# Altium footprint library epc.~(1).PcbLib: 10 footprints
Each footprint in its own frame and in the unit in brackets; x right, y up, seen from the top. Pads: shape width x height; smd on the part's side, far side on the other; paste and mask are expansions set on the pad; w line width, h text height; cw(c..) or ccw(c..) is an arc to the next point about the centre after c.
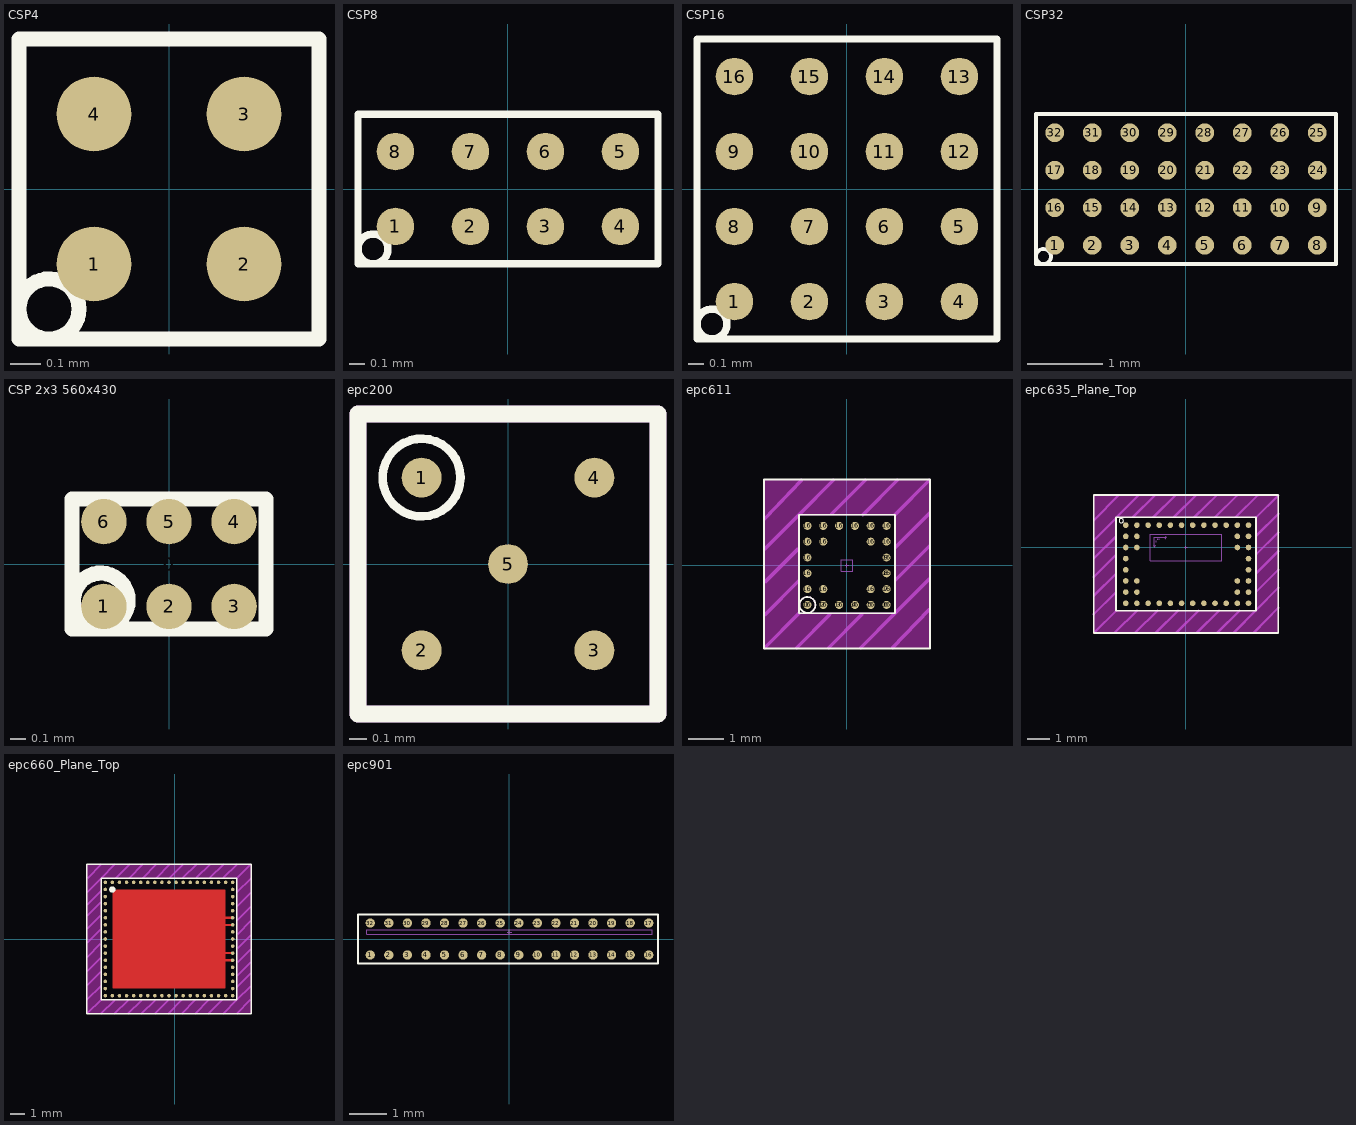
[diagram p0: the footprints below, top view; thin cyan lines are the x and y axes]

## CSP4 [mm] "CSP4 Dual Photodiode"
height 0.3
pads (4):
  round 0.25 smd mask+0.05: 1(-0.25,-0.25) 2(0.25,-0.25) 3(0.25,0.25) 4(-0.25,0.25)
Top Overlay:
  circle w0.05: c-0.4,-0.4 r0.1
  lines w0.05: -0.5,-0.5 -0.5,0.5 0.5,0.5 0.5,-0.5 -0.5,-0.5
3D body "epc300-CSP4_001.STEP": height 0.23, standoff -0.01, extent -0.5,-0.5 0.5,0.5

## CSP8 [mm] "CSP8 Quad Photodiode-Array"
height 0.3
pads (8):
  round 0.25 smd mask+0.05: 1(-0.75,-0.25) 2(-0.25,-0.25) 3(0.25,-0.25) 4(0.75,-0.25) 5(0.75,0.25) 6(0.25,0.25) 7(-0.25,0.25) 8(-0.75,0.25)
Top Overlay:
  circle w0.05: c-0.9,-0.4 r0.1
  lines w0.05: -1,-0.5 1,-0.5 1,0.5 -1,0.5 -1,-0.5
3D body "epc310-CSP8-001.STEP": height 0.24, standoff 0, extent -1,-0.5 1,0.5

## CSP16 [mm] "CSP16 Octa Photodiode-Array"
height 0.3
pads (16):
  round 0.25 smd mask+0.05: 1(-0.75,-0.75) 2(-0.25,-0.75) 3(0.25,-0.75) 4(0.75,-0.75) 5(0.75,-0.25) 6(0.25,-0.25) 7(-0.25,-0.25) 8(-0.75,-0.25) 9(-0.75,0.25) 10(-0.25,0.25) 11(0.25,0.25) 12(0.75,0.25) 13(0.75,0.75) 14(0.25,0.75) 15(-0.25,0.75) 16(-0.75,0.75)
Top Overlay:
  circle w0.05: c-0.9,-0.9 r0.1
  lines w0.05: -1,-1 -1,1 1,1 1,-1 -1,-1
3D body "epc320-CSP16-001.STEP": height 0.24, standoff 0, extent -1,-1 1,1

## CSP32 [mm] "CSP16 hexa Photodiode-Array"
height 0.3
pads (32):
  round 0.25 smd mask+0.05: 1(-1.75,-0.75) 2(-1.25,-0.75) 3(-0.75,-0.75) 4(-0.25,-0.75) 5(0.25,-0.75) 6(0.75,-0.75) 7(1.25,-0.75) 8(1.75,-0.75) 9(1.75,-0.25) 10(1.25,-0.25) 11(0.75,-0.25) 12(0.25,-0.25) 13(-0.25,-0.25) 14(-0.75,-0.25) 15(-1.25,-0.25) 16(-1.75,-0.25) 17(-1.75,0.25) 18(-1.25,0.25) 19(-0.75,0.25) 20(-0.25,0.25) 21(0.25,0.25) 22(0.75,0.25) 23(1.25,0.25) 24(1.75,0.25) 25(1.75,0.75) 26(1.25,0.75) 27(0.75,0.75) 28(0.25,0.75) 29(-0.25,0.75) 30(-0.75,0.75) 31(-1.25,0.75) 32(-1.75,0.75)
Top Overlay:
  circle w0.05: c-1.9,-0.9 r0.1
  lines w0.05: -2,-1 -2,1 2,1 2,-1 -2,-1
3D body "epc330-CSP32-001.STEP": height 0.24, standoff 0, extent -2,-1 2,1

## CSP 2x3 560x430 [mm] "CSP 2x3"
height 0.3
pads (7):
  rect 1.98x1.56 on Top Solder: 0(0,0)
  round 0.3 smd paste+0 mask-0.16: 1(-0.43,-0.28)
  round 0.3 smd paste+0 mask-1.6: 2(0,-0.28) 3(0.43,-0.28) 4(0.43,0.28) 5(0,0.28)
  round 0.3 smd paste+0 mask-0.3: 6(-0.43,0.28)
Top Overlay:
  circle w0.1: c-0.45,-0.24 r0.18
  lines w0.1: -0.64,-0.43 0.64,-0.43 0.64,0.43 -0.64,0.43 -0.64,-0.43
3D body: height 0.3, standoff 0.2, extent -0.6,-0.45 0.575,0.425
3D body: height 0.2, standoff 0, extent -0.526,-0.374 -0.327,-0.175
3D body: height 0.2, standoff 0, extent -0.101,-0.375 0.098,-0.175
3D body: height 0.2, standoff 0, extent 0.325,-0.375 0.524,-0.175
3D body: height 0.2, standoff 0, extent 0.326,0.175 0.525,0.375
3D body: height 0.2, standoff 0, extent -0.1,0.175 0.099,0.375
3D body: height 0.2, standoff 0, extent -0.525,0.175 -0.326,0.374

## epc200 [mm]
pads (5):
  round 0.23 smd paste+0.035 mask+0.05: 1(-0.5,0.5) 2(-0.5,-0.5) 3(0.5,-0.5) 4(0.5,0.5) 5(0,0)
Top Overlay:
  circle w0.05: c-0.5,0.5 r0.225
  lines w0.1: -0.867,-0.867 -0.867,0.867 0.867,0.867 0.867,-0.867 -0.867,-0.867
Mechanical 4:
  lines w0.1: -0.867,-0.867 -0.867,0.867 0.867,0.867 0.867,-0.867 -0.867,-0.867
3D body "epc200-CSP5.STEP": height 0.24, standoff -0.01, extent -0.875,-0.875 0.875,0.875

## epc611 [mm]
height 0.25
pads (49):
  round 0.229 smd paste-0.254 mask+0.111: 1(-1.125,-1.125) 2(-0.675,-1.125) 3(-0.225,-1.125) 4(0.225,-1.125) 5(0.675,-1.125) 6(1.125,-1.125) 7(1.125,-0.675) 8(1.125,-0.225) 9(1.125,0.225) 10(1.125,0.675) 11(1.125,1.125) 12(0.675,1.125) 13(0.225,1.125) 14(-0.225,1.125) 15(-0.675,1.125) 16(-1.125,1.125) 17(-1.125,0.675) 18(-1.125,0.225) 19(-1.125,-0.225) 20(-1.125,-0.675) 21(-0.675,-0.675) 22(0.675,-0.675) 23(0.675,0.675) 24(-0.675,0.675)
  round 0.3 on Top Paste paste+0.057 mask-0.508: 16(-1.125,-1.125) 16(-1.125,-0.675) 16(-1.125,-0.225) 16(-1.125,0.225) 16(-1.125,1.125) 16(-0.675,-1.125) 16(-0.675,-0.675) 16(-0.675,0.675) 16(-0.675,1.125) 16(-0.225,-1.125) 16(-0.225,1.125) 16(0.225,1.125) 16(0.675,-1.125) 16(0.675,-0.675) 16(0.675,0.675) 16(0.675,1.125) 16(1.125,-1.125) 16(1.125,-0.675) 16(1.125,-0.225) 16(1.125,0.225) 16(1.125,0.675) 16(1.125,1.125)
  round 0.3 on Top Paste paste+0.057 mask-0.108: 16(-1.125,0.675)
  round 0.3 on Top Paste paste+0.057 mask+0.051: 16(0.225,-1.125)
  round 0.229 smd paste-0.254 mask+0.051: 21(-0.675,-0.675)
Top Layer keep-out:
  region: -2.365,2.445 -2.365,-2.365 -1.365,-2.365 -1.365,2.445
  region: 2.365,2.445 -2.365,2.445 -2.365,1.445 2.365,1.445
  region: 2.365,-2.365 2.365,2.445 1.365,2.445 1.365,-2.365
  rectangle: -2.365,-2.365 2.365,-1.365
Top Overlay:
  circle w0.05: c-1.125,-1.125 r0.225
  lines w0.05: -2.365,-2.365 -2.365,2.445 2.365,2.445 2.365,-2.365 -2.365,-2.365 ; -1.365,-1.365 1.365,-1.365 1.365,1.445 -1.365,1.445 -1.365,-1.365
Mechanical 2:
  lines w0.1: -2.343,-2.343 -1.365,-1.365 ; -2.343,0.467 -1.365,1.445 -0.387,2.423 ; -2.338,1.333 -1.297,2.423 ; -2.336,-1.404 -1.388,-0.456 ; -2.335,-0.471 -1.41,0.454 ; -1.433,-2.343 -0.487,-1.397 ; -0.523,-2.343 0.426,-1.393 ; -0.429,1.471 0.522,2.423 ; 0.387,-2.343 1.365,-1.365 2.343,-0.387 ; 0.454,1.445 1.432,2.423 ; 1.297,-2.343 2.333,-1.258 ; 1.365,1.445 2.343,2.423 ; 1.385,-0.413 2.343,0.545 ; 1.389,0.523 2.347,1.481
  text "ATTENTION:  / 1mm clearance arount the epc611.  / Don't place components within this frame." at -2.45,-3.97 h0.25
Mechanical 4:
  circle w0.05: c-1.125,-1.125 r0.225
  lines w0.01: -0.05,0 0.05,0 ; 0,-0.05 0,0.05 ; -0.16,-0.16 0.16,-0.16 0.16,0.16 -0.16,0.16 -0.16,-0.16
  lines w0.05: -1.365,-1.365 -1.365,1.445 1.365,1.445 1.365,-1.365 -1.365,-1.365
  text "col7" at 0.2,-0.505 h0.2
  text "row7" at 0.21,-0.2 h0.2
  text "row0" at 0.21,0.12 h0.2
  text "col0" at -0.115,-0.505 h0.2
3D body: height 0.2, standoff 0, extent 1.026,0.125 1.224,0.325
3D body: height 0.2, standoff 0, extent 1.026,-0.325 1.224,-0.125
3D body: height 0.2, standoff 0, extent 1.026,-0.775 1.224,-0.575
3D body: height 0.2, standoff 0, extent 0.576,-0.775 0.774,-0.575
3D body: height 0.2, standoff 0, extent -0.774,-0.775 -0.576,-0.575
3D body: height 0.2, standoff 0, extent -1.224,-0.775 -1.026,-0.575
3D body: height 0.2, standoff 0, extent -1.224,-0.325 -1.026,-0.125
3D body: height 0.2, standoff 0, extent -1.224,0.125 -1.026,0.325
3D body: height 0.2, standoff 0, extent -1.224,0.575 -1.026,0.775
3D body: height 0.2, standoff 0, extent -0.774,0.575 -0.576,0.775
3D body: height 0.2, standoff 0, extent 0.576,0.575 0.774,0.775
3D body: height 0.2, standoff 0, extent 1.026,0.575 1.224,0.775
3D body: height 0.2, standoff 0, extent 0.126,1.025 0.324,1.225
3D body: height 0.2, standoff 0, extent -0.324,1.025 -0.126,1.225
3D body: height 0.2, standoff 0, extent -0.774,1.025 -0.576,1.225
3D body: height 0.2, standoff 0, extent -1.224,1.025 -1.026,1.225
3D body: height 0.2, standoff 0, extent -1.224,-1.225 -1.026,-1.025
3D body: height 0.2, standoff 0, extent 0.576,-1.225 0.774,-1.025
3D body: height 0.2, standoff 0, extent 1.026,-1.225 1.224,-1.025
3D body: height 0.2, standoff 0, extent 1.026,1.025 1.224,1.225
3D body: height 0.2, standoff 0, extent 0.576,1.025 0.774,1.225
3D body: height 0.2, standoff 0, extent -0.324,-1.225 -0.126,-1.025
3D body: height 0.2, standoff 0, extent 0.126,-1.225 0.324,-1.025
3D body: height 0.2, standoff 0, extent -0.774,-1.225 -0.576,-1.025
3D body: height 0.25, standoff 0.19, extent -1.365,-1.365 1.365,1.445

## epc635_Plane_Top [mm] "CSP44 epc635_PL_Top"
height 0.26
pads (44):
  round 0.25 smd paste+0.025 mask+0.05: 1(-2.7,1) 2(-2.7,0.5) 3(-2.7,0) 4(-2.7,-0.5) 5(-2.7,-1) 6(-2.7,-1.5) 7(-2.7,-2) 8(-2.7,-2.5) 9(-2.2,-2.5) 10(-1.7,-2.5) 11(-1.2,-2.5) 12(-0.7,-2.5) 13(-0.2,-2.5) 14(0.3,-2.5) 15(0.8,-2.5) 16(1.3,-2.5) 17(1.8,-2.5) 18(2.3,-2.5) 19(2.8,-2.5) 20(2.8,-2) 21(2.8,-1.5) 22(2.8,-1) 23(2.8,-0.5) 24(2.8,0) 25(2.8,0.5) 26(2.8,1) 27(2.3,1) 28(1.8,1) 29(1.3,1) 30(0.8,1) 31(0.3,1) 32(-0.2,1) 33(-0.7,1) 34(-1.2,1) 35(-1.7,1) 36(-2.2,1) 37(-2.2,0.5) 38(-2.2,0) 39(-2.2,-1.5) 40(-2.2,-2) 41(2.3,-2) 42(2.3,-1.5) 43(2.3,0) 44(2.3,0.5)
Top Layer keep-out:
  rectangle: -4.13,-3.83 4.13,-2.83
  region: 4.13,2.35 -4.13,2.35 -4.13,1.35 4.13,1.35
  region: -4.13,2.35 -4.13,-3.83 -3.13,-3.83 -3.13,2.35
  region: 4.13,-3.83 4.13,2.35 3.13,2.35 3.13,-3.83
Top Overlay:
  circle w0.05: c-2.9,1.2 r0.1
  lines w0.08: -4.13,-3.83 4.13,-3.83 4.13,2.35 -4.13,2.35 -4.13,-3.83 ; -3.13,-2.83 3.13,-2.83 3.13,1.35 -3.13,1.35 -3.13,-2.83
Mechanical 2:
  lines w0.1: -4.133,-2.994 -3.146,-2.017 ; -4.133,-1.318 -3.146,-0.341 ; -4.12,-2.156 -3.133,-1.179 ; -4.12,-0.48 -3.133,0.497 ; -4.12,0.32 -2.143,2.327 ; -4.12,1.22 -3.038,2.327 ; -4.108,-3.808 -3.13,-2.83 -3.12,-2.83 ; -3.187,-3.807 -2.2,-2.83 ; -2.376,1.365 -1.388,2.342 ; -2.267,-3.807 -1.28,-2.83 ; -1.456,1.365 -0.468,2.342 ; -1.347,-3.807 -0.36,-2.83 ; -0.536,1.365 0.452,2.342 ; -0.427,-3.807 0.56,-2.83 ; 0.384,1.365 1.372,2.342 ; 0.493,-3.807 1.48,-2.83 ; 1.304,1.365 2.292,2.342 ; 1.413,-3.807 2.4,-2.83 ; 2.152,-3.808 4.13,-1.8 ; 2.225,1.365 3.212,2.342 ; 3.048,-3.807 4.13,-2.7 ; 3.143,-1.977 4.13,-1 ; 3.143,-0.301 4.13,0.676 ; 3.143,1.352 4.13,2.329 ; 3.156,-1.139 4.143,-0.162 ; 3.156,0.537 4.143,1.514
  text "ATTENTION:  / 1mm clearance arount the epc635.  / Don't place components within this frame." at -4.215,-5.435 h0.25
Mechanical 4:
  lines w0.01: -1.476,0.094 -1.417,0.034 -1.357,0.094 ; -1.416,0.094 -1.416,0.454 -0.936,0.454 ; -1.348,0.256 -1.322,0.256 ; -1.348,0.306 -1.322,0.306 ; -1.272,0.357 -1.272,0.383 ; -1.195,0.357 -1.195,0.383 ; -0.936,0.394 -0.876,0.454 -0.936,0.514 ; -0.06,0 0.06,0 ; 0,-0.06 0,0.06 ; -1.6,-0.6 1.6,-0.6 1.6,0.6 -1.6,0.6 -1.6,-0.6
  text "0" at -1.373,0.357 h0.08
  text "160" at -1.145,0.357 h0.08
  text "60" at -1.373,0.129 h0.08
  text "y" at -1.449,-0.049 h0.08
  text "x" at -0.84,0.433 h0.08
3D body "epc635-CSP44-003.STEP": height 0.24, standoff 0, extent -3.12,-2.83 3.14,1.35

## epc660_Plane_Top [mm] "CSP68 epc660_PL_Top"
height 0.26
pads (68):
  round 0.25 smd paste+0.025 mask+0.05: 1(-4.9,4) 2(-4.9,3.5) 3(-4.9,3) 4(-4.9,2.5) 5(-4.9,2) 6(-4.9,1.5) 7(-4.9,1) 8(-4.9,0.5) 9(-4.9,0) 10(-4.9,-0.5) 11(-4.9,-1) 12(-4.9,-1.5) 13(-4.9,-2) 14(-4.9,-2.5) 15(-4.9,-3) 16(-4.9,-3.5) 17(-4.9,-4) 18(-4.4,-4) 19(-3.9,-4) 20(-3.4,-4) 21(-2.9,-4) 22(-2.4,-4) 23(-1.9,-4) 24(-1.4,-4) 25(-0.9,-4) 26(-0.4,-4) 27(0.1,-4) 28(0.6,-4) 29(1.1,-4) 30(1.6,-4) 31(2.1,-4) 32(2.6,-4) 33(3.1,-4) 34(3.6,-4) 35(4.1,-4) 36(4.1,-3.5) 37(4.1,-3) 38(4.1,-2.5) 39(4.1,-2) 40(4.1,-1.5) 41(4.1,-1) 42(4.1,-0.5) 43(4.1,0) 44(4.1,0.5) 45(4.1,1) 46(4.1,1.5) 47(4.1,2) 48(4.1,2.5) 49(4.1,3) 50(4.1,3.5) 51(4.1,4) 52(3.6,4) 53(3.1,4) 54(2.6,4) 55(2.1,4) 56(1.6,4) 57(1.1,4) 58(0.6,4) 59(0.1,4) 60(-0.4,4) 61(-0.9,4) 62(-1.4,4) 63(-1.9,4) 64(-2.4,4) 65(-2.9,4) 66(-3.4,4) 67(-3.9,4) 68(-4.4,4)
Top Layer:
  rectangle: -4.4,-3.5 3.6,3.5
  lines w0.15: 3.2,-1.5 4.1,-1.5 ; 3.2,-1 4.1,-1 ; 3.2,1 4.1,1 ; 3.2,1.5 4.1,1.5
Top Layer keep-out:
  region: -6.2,5.3 -6.2,-5.3 -5.2,-5.3 -5.2,5.3
  region: 5.4,5.3 -6.2,5.3 -6.2,4.3 5.4,4.3
  region: 5.4,-5.3 5.4,5.3 4.4,5.3 4.4,-5.3
  rectangle: -6.2,-5.3 5.4,-4.3
Top Overlay:
  circle w0.254: c-4.4,3.5 r0.1
  lines w0.1: -5.2,-4.3 4.4,-4.3 4.4,4.3 -5.2,4.3 ; -5.2,-4.285 -5.2,4.285 ; -6.2,-5.3 -6.2,5.3 5.4,5.3 5.4,-5.3 -6.2,-5.3
Mechanical 2:
  lines w0.1: -6.2,-4.285 -5.205,-3.292 ; -6.194,0.716 -5.274,1.635 ; -6.191,-3.277 -5.219,-2.307 ; -6.191,-0.28 -5.26,0.649 ; -6.192,2.416 -5.196,3.409 ; -6.19,-1.278 -5.246,-0.336 ; -6.186,1.629 -5.233,2.58 ; -6.185,-2.272 -5.232,-1.321 ; -6.177,-5.262 -5.2,-4.285 ; -6.177,3.308 -5.2,4.285 ; -6.149,4.298 -5.174,5.273 ; -5.217,-5.3 -4.24,-4.323 ; -5.2,4.3 -4.223,5.277 ; -4.265,-5.296 -3.29,-4.321 ; -4.163,4.299 -3.188,5.274 ; -3.315,-5.293 -2.34,-4.318 ; -3.213,4.302 -2.238,5.277 ; -2.364,-5.29 -1.389,-4.314 ; -2.262,4.305 -1.287,5.28 ; -1.414,-5.286 -0.439,-4.311 ; -1.312,4.308 -0.337,5.283 ; -0.463,-5.283 0.512,-4.308 ; -0.361,4.311 0.614,5.286 ; 0.487,-5.28 1.462,-4.305 ; 0.589,4.314 1.564,5.29 ; 1.438,-5.277 2.413,-4.302 ; 1.54,4.318 2.515,5.293 ; 2.388,-5.274 3.363,-4.299 ; 2.49,4.321 3.465,5.296 ; 3.423,-5.277 4.4,-4.3 5.377,-3.323 ; 3.44,4.323 4.417,5.3 ; 4.374,-5.273 5.349,-4.298 ; 4.396,-3.409 5.392,-2.416 ; 4.4,4.3 5.377,5.277 ; 4.405,3.292 5.4,4.285 ; 4.419,2.307 5.391,3.277 ; 4.432,1.321 5.385,2.272 ; 4.433,-2.58 5.386,-1.629 ; 4.446,0.336 5.39,1.278 ; 4.46,-0.649 5.391,0.28 ; 4.474,-1.635 5.394,-0.716
  text "ATTENTION:  / 1mm clearance arount the epc660.  / Don't place components within this frame." at -6.285,-6.905 h0.25
Mechanical 4:
  lines w0.01: -2.976,1.594 -2.917,1.534 -2.857,1.594 ; -2.916,1.594 -2.916,1.954 -2.336,1.954 ; -2.848,1.756 -2.822,1.756 ; -2.848,1.806 -2.822,1.806 ; -2.772,1.857 -2.772,1.883 ; -2.695,1.857 -2.695,1.883 ; -2.336,1.894 -2.276,1.954 -2.336,2.014 ; -0.06,0 0.06,0 ; 0,-0.06 0,0.06 ; -3.2,-2.4 -3.2,2.4 3.2,2.4 3.2,-2.4 -3.2,-2.4
  text "0" at -2.873,1.857 h0.08
  text "320" at -2.645,1.857 h0.08
  text "240" at -2.873,1.629 h0.08
  text "y" at -2.949,1.451 h0.08
  text "x" at -2.24,1.933 h0.08
  text "PIXEL #320" at 2.038,-2.184 h0.1
  text "PIXEL #0" at -2.991,2.108 h0.1
3D body "epc660 19x17 Pads(1).STEP": height 0.27, standoff -0.05, extent -5.2,-4.3 4.46,4.36

## epc901 [mm]
pads (32):
  round 0.25 smd paste+0.025 mask+0.05: 1(-3.75,-0.43) 2(-3.25,-0.43) 3(-2.75,-0.43) 4(-2.25,-0.43) 5(-1.75,-0.43) 6(-1.25,-0.43) 7(-0.75,-0.43) 8(-0.25,-0.43) 9(0.25,-0.43) 10(0.75,-0.43) 11(1.25,-0.43) 12(1.75,-0.43) 13(2.25,-0.43) 14(2.75,-0.43) 15(3.25,-0.43) 16(3.75,-0.43) 17(3.75,0.43) 18(3.25,0.43) 19(2.75,0.43) 20(2.25,0.43) 21(1.75,0.43) 22(1.25,0.43) 23(0.75,0.43) 24(0.25,0.43) 25(-0.25,0.43) 26(-0.75,0.43) 27(-1.25,0.43) 28(-1.75,0.43) 29(-2.25,0.43) 30(-2.75,0.43) 31(-3.25,0.43) 32(-3.75,0.43)
Top Overlay:
  lines w0.05: -4.08,-0.66 -4.08,-0.25 -4.08,0.25 -4.08,0.66 4,0.66 4,-0.66 -4.08,-0.66
Mechanical 4:
  lines w0.01: -0.06,0.183 0.06,0.183 ; 0,0.123 0,0.243 ; -3.839,0.123 -3.839,0.243 3.839,0.243 3.839,0.123 -3.839,0.123
  text "PIXEL #1023" at 2.739,0.133 h0.1
  text "PIXEL #0" at -3.8,0.133 h0.1
3D body "epc901-CSP32-033.STEP": height 0.24, standoff 0, extent -4.08,-0.662 4,0.662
